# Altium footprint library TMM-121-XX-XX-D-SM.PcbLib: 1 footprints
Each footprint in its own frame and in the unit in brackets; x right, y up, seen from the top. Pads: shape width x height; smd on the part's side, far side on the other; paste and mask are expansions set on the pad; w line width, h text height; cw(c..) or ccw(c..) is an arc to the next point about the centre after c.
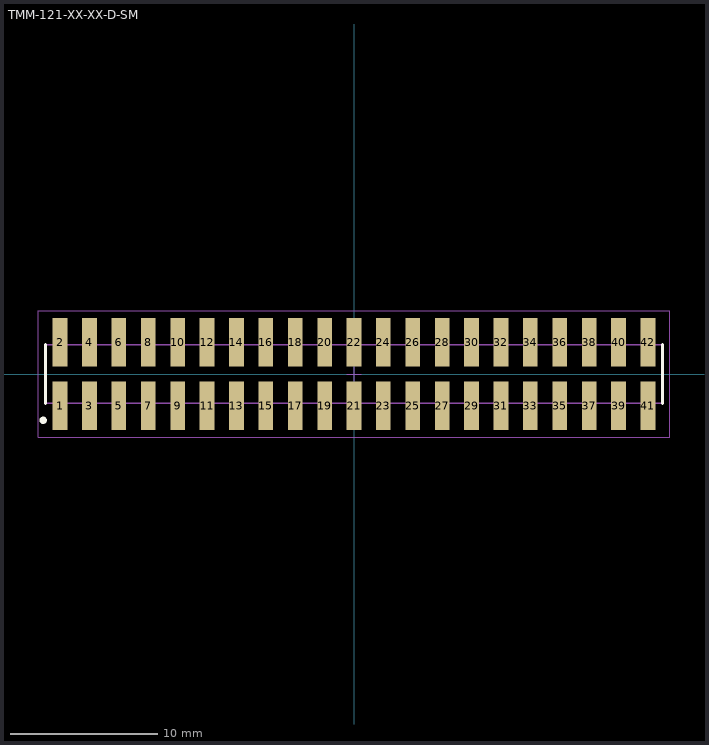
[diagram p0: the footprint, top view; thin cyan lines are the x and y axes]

## TMM-121-XX-XX-D-SM [mm] "2.00mm pitch, 42 pin, terminal strip; double row, SMT"
height 2.77
pads (42):
  rect 1x3.3 smd mask+0: 1(-20,-2.15) 2(-20,2.15) 3(-18,-2.15) 4(-18,2.15) 5(-16,-2.15) 6(-16,2.15) 7(-14,-2.15) 8(-14,2.15) 9(-12,-2.15) 10(-12,2.15) 11(-10,-2.15) 12(-10,2.15) 13(-8,-2.15) 14(-8,2.15) 15(-6,-2.15) 16(-6,2.15) 17(-4,-2.15) 18(-4,2.15) 19(-2,-2.15) 20(-2,2.15) 21(0,-2.15) 22(0,2.15) 23(2,-2.15) 24(2,2.15) 25(4,-2.15) 26(4,2.15) 27(6,-2.15) 28(6,2.15) 29(8,-2.15) 30(8,2.15) 31(10,-2.15) 32(10,2.15) 33(12,-2.15) 34(12,2.15) 35(14,-2.15) 36(14,2.15) 37(16,-2.15) 38(16,2.15) 39(18,-2.15) 40(18,2.15) 41(20,-2.15) 42(20,2.15)
Top Overlay:
  circle w0.25: c-21.15,-3.15 r0.125
  lines w0.2: -21,-2 -21,2 ; 21,-2 21,2
Mechanical 12:
  lines w0.001: -21,-2 21,-2 21,2 -21,2 -21,-2
Mechanical 13:
  lines w0.1: -21,-2 21,-2 21,2 -21,2 -21,-2
  text ".Designator" at 0,-0.127 h1.52
Mechanical 15:
  lines w0.05: -0.5,0 0.5,0 ; 0,-0.5 0,0.5 ; -21.5,-4.3 21.5,-4.3 21.5,4.3 -21.5,4.3 -21.5,-4.3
